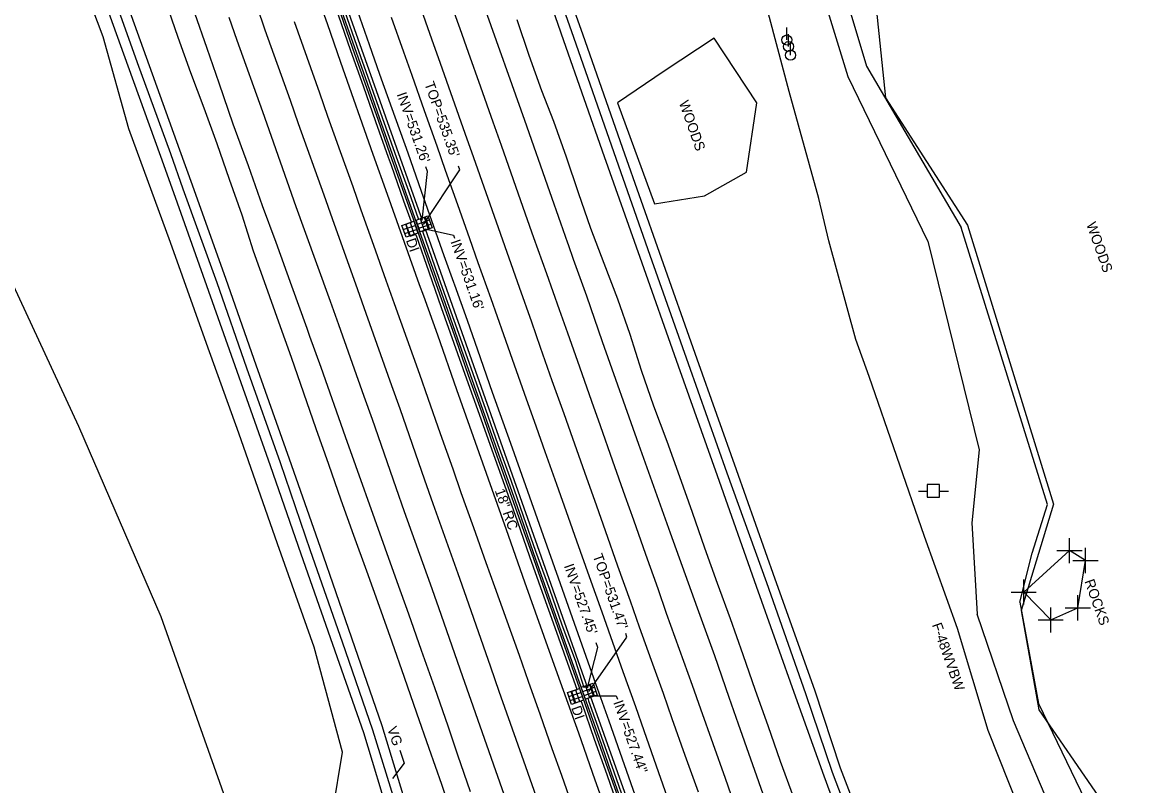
# Model space of a CAD drawing. Extents: x 2004847 to 2009016, y 1134161 to 1140101.
# Drawn here: x 2006650.7 to 2007096, y 1134403 to 1134706.5 of the extents above; entities that cross this region are included whole.
import ezdxf

# ---------------------------------------------------------------- set-up
doc = ezdxf.new("R2010")
doc.units = 0
for name, color, linetype in [('RD_EX_Conc', 7, 'Continuous'), ('RD_EX_DR_Inlet', 7, 'Continuous'), ('RD_EX_DR_Inlet_txCode', 7, 'Continuous'), ('RD_EX_DR_Pipe', 7, 'Continuous'), ('RD_EX_DR_Pipe_txCode', 7, 'Continuous'), ('RD_EX_Driveway', 7, 'Continuous'), ('RD_EX_DV_Prop_txCode', 7, 'Continuous'), ('RD_EX_Fence_Other', 7, 'Continuous'), ('RD_EX_Misc', 7, 'Continuous'), ('RD_EX_Pavement_Markings', 7, 'Continuous'), ('RD_EX_Road', 7, 'Continuous'), ('RD_EX_UT', 7, 'Continuous'), ('RD_EX_VEG', 7, 'Continuous'), ('RD_Sketch3', 7, 'Continuous')]:
    doc.layers.add(name, color=color, linetype=linetype)

msp = doc.modelspace()

# ---------------------------------------------------------------- linework, layer by layer
at = {"layer": 'RD_EX_Conc'}
for points in [[(2007008.76, 1134333.65), (2006993.63, 1134363.82), (2006975.89, 1134409.97), (2006965.78, 1134441.02), (2006950.02, 1134485.15), (2006934.64, 1134528.55), (2006918.96, 1134572.55), (2006904.01, 1134614.93), (2006889.45, 1134656.34), (2006873.52, 1134701.79), (2006859.53, 1134740.78), (2006845, 1134783.14), (2006828.98, 1134829.04), (2006813.77, 1134872.83), (2006798.81, 1134915.62), (2006782.15, 1134963.38), (2006767.46, 1135005.24), (2006753.34, 1135046.25), (2006752.31, 1135048.89), (2006751.51, 1135051.2), (2006736.87, 1135093.18), (2006721.7, 1135136.82), (2006709.9, 1135170.59)], [(2007001.61, 1134330.02), (2006986.35, 1134360.57), (2006969.5, 1134406.75), (2006958.22, 1134438.26), (2006942.49, 1134482.23), (2006927.03, 1134526.16), (2006911.49, 1134569.75), (2006896.31, 1134613.04), (2006882.16, 1134653.08), (2006865.99, 1134699.12), (2006852.4, 1134738.21), (2006837.28, 1134781.15), (2006821.3, 1134826.88), (2006806.03, 1134870.56), (2006791.16, 1134913.28), (2006774.61, 1134960.65), (2006760.24, 1135002.17), (2006744.89, 1135045.85), (2006729.14, 1135091.12), (2006713.78, 1135134.81), (2006702.17, 1135168.35)], [(2006812.01, 1134352.55), (2006804.85, 1134390.29), (2006793.78, 1134426.87), (2006781.64, 1134461.67), (2006769.18, 1134497.73), (2006756.9, 1134532.82), (2006743.7, 1134570.21), (2006731.7, 1134604.22), (2006718.31, 1134641.74), (2006713.33, 1134655.71), (2006700.01, 1134692.45), (2006688.72, 1134724.37), (2006675.5, 1134761.9)], [(2006804.07, 1134351.71), (2006797.18, 1134388.56), (2006786.48, 1134424.09), (2006774.14, 1134459.12), (2006761.55, 1134495.03), (2006749.36, 1134530.2), (2006736.12, 1134567.64), (2006724.06, 1134601.67), (2006710.86, 1134638.74), (2006705.69, 1134653.17), (2006692.76, 1134689), (2006681.14, 1134721.57), (2006668.03, 1134759.07)], [(2006777.01, 1134710.4), (2006782, 1134696.25), (2006787.02, 1134682.08), (2006792.02, 1134667.97), (2006796.98, 1134653.82), (2006802.35, 1134638.76), (2006808, 1134622.75), (2006813.01, 1134608.57), (2006818.04, 1134594.46), (2006822.99, 1134580.35), (2006827.98, 1134566.17), (2006833.03, 1134552.04), (2006838.05, 1134537.91), (2006843.04, 1134523.78), (2006848.09, 1134509.65), (2006853.08, 1134495.53), (2006858.41, 1134480.47), (2006863.41, 1134466.29), (2006868.44, 1134452.16), (2006874.13, 1134436.14), (2006879.1, 1134422.03), (2006884.12, 1134407.89), (2006889.12, 1134393.75)], [(2006777.73, 1134710.65), (2006782.72, 1134696.51), (2006787.75, 1134682.34), (2006792.72, 1134668.22), (2006797.72, 1134654.08), (2006803.07, 1134639.02), (2006808.72, 1134623), (2006813.75, 1134608.84), (2006818.74, 1134594.71), (2006823.73, 1134580.61), (2006828.73, 1134566.44), (2006833.75, 1134552.3), (2006838.79, 1134538.17), (2006843.78, 1134524.04), (2006848.8, 1134509.9), (2006853.79, 1134495.78), (2006859.1, 1134480.71), (2006864.14, 1134466.55), (2006869.15, 1134452.41), (2006874.85, 1134436.4), (2006879.82, 1134422.28), (2006884.82, 1134408.14), (2006889.83, 1134394)]]:
    msp.add_lwpolyline(points, dxfattribs=at)
at = {"layer": 'RD_EX_DR_Inlet'}
for p, q in [((2006807.76, 1134626.29), (2006812.49, 1134627.91)), ((2006808.81, 1134628.45), (2006810.44, 1134623.72)), ((2006810.42, 1134629), (2006812.04, 1134624.27)), ((2006802.15, 1134624.15), (2006806.88, 1134625.77)), ((2006802.7, 1134622.54), (2006807.43, 1134624.16)), ((2006803.21, 1134626.31), (2006804.83, 1134621.58)), ((2006804.81, 1134626.86), (2006806.44, 1134622.13)), ((2006808.31, 1134624.68), (2006813.04, 1134626.3)), ((2006869, 1134440.63), (2006870.62, 1134435.9)), ((2006870.61, 1134441.18), (2006872.23, 1134436.45)), ((2006873.46, 1134440.52), (2006878.19, 1134442.14)), ((2006874.02, 1134438.91), (2006878.75, 1134440.53)), ((2006874.52, 1134442.68), (2006876.14, 1134437.95)), ((2006876.13, 1134443.23), (2006877.75, 1134438.5)), ((2006867.94, 1134438.47), (2006872.67, 1134440.09)), ((2006868.5, 1134436.86), (2006873.22, 1134438.48))]:
    msp.add_line(p, q, dxfattribs=at)
for points in [[(2006803.22, 1134621.02), (2006801.6, 1134625.75), (2006806.33, 1134627.38), (2006807.95, 1134622.65)], [(2006808.83, 1134623.17), (2006807.21, 1134627.9), (2006811.94, 1134629.52), (2006813.56, 1134624.79)], [(2006869.01, 1134435.35), (2006867.39, 1134440.08), (2006872.12, 1134441.7), (2006873.74, 1134436.97)], [(2006874.54, 1134437.4), (2006872.91, 1134442.13), (2006877.64, 1134443.75), (2006879.26, 1134439.02)]]:
    msp.add_lwpolyline(points, close=True, dxfattribs=at)
at = {"layer": 'RD_EX_DR_Inlet_txCode'}
for points in [[(2006809.6, 1134627.85), (2006811.77, 1134647.25), (2006811.16, 1134648.99)], [(2006810.19, 1134626.14), (2006824.59, 1134647.89), (2006824.1, 1134649.29)], [(2006810.77, 1134624.41), (2006822.1, 1134621.88), (2006822.53, 1134620.66)], [(2006875.91, 1134440.4), (2006891.06, 1134462.06), (2006890.57, 1134463.46)], [(2006875.37, 1134441.93), (2006879.43, 1134457.98), (2006878.79, 1134459.78)], [(2006876.41, 1134438.8), (2006886.8, 1134438.69), (2006887.26, 1134437.4)]]:
    msp.add_lwpolyline(points, dxfattribs=at)
at = {"layer": 'RD_EX_DR_Pipe'}
for p, q in [((2006739.57, 1134825.25), (2006809.6, 1134627.85)), ((2006810.77, 1134624.41), (2006875.37, 1134441.93)), ((2006876.41, 1134438.8), (2006910.37, 1134343.42))]:
    msp.add_line(p, q, dxfattribs=at)
at = {"layer": 'RD_EX_Driveway'}
for points in [[(2007010.65, 1134619.47), (2006979.03, 1134684.79), (2006961.64, 1134741.36)], [(2006970.9, 1134740.44), (2006986.22, 1134689.04), (2007023.87, 1134624.93)], [(2007047.24, 1134476.04), (2007052.16, 1134495.5), (2007058.26, 1134514.81), (2007023.87, 1134624.93)], [(2007010.65, 1134619.47), (2007031.06, 1134536.55), (2007028.2, 1134507.51), (2007030.28, 1134471.18)], [(2007047.24, 1134476.04), (2007054.6, 1134435.72), (2007073.17, 1134397.21), (2007088.83, 1134358.42), (2007096.03, 1134334.59)], [(2007079.8, 1134330.74), (2007073.16, 1134353.09), (2007060.64, 1134391.35), (2007044.77, 1134428.83), (2007030.28, 1134471.18)]]:
    msp.add_lwpolyline(points, dxfattribs=at)
at = {"layer": 'RD_EX_DV_Prop_txCode'}
for p, q in [((2007066.97, 1134491.45), (2007066.97, 1134501.45)), ((2007061.97, 1134496.45), (2007071.97, 1134496.45)), ((2007073.32, 1134487.51), (2007073.32, 1134497.51)), ((2007068.32, 1134492.51), (2007078.32, 1134492.51)), ((2007048.78, 1134474.99), (2007048.78, 1134484.99)), ((2007043.78, 1134479.99), (2007053.78, 1134479.99)), ((2007070.27, 1134468.75), (2007070.27, 1134478.75)), ((2007059.5, 1134463.91), (2007059.5, 1134473.91)), ((2007065.27, 1134473.75), (2007075.27, 1134473.75)), ((2007054.5, 1134468.91), (2007064.5, 1134468.91))]:
    msp.add_line(p, q, dxfattribs=at)
at = {"layer": 'RD_EX_Fence_Other'}
for points in [[(2007063.77, 1134349.09), (2007051.32, 1134382.98), (2007034.66, 1134424.99), (2007022.46, 1134465.49), (2007009.27, 1134502.08), (2006987.27, 1134565.71), (2006982.09, 1134580.37), (2006971.28, 1134619.61), (2006967.26, 1134636.51), (2006955.53, 1134679.01), (2006933.1, 1134763.45), (2006921.61, 1134808.45), (2006913.35, 1134838.48), (2006889.85, 1134911.88), (2006879.83, 1134940.33), (2006864.22, 1134985.13), (2006847.99, 1135029.35), (2006842.47, 1135045.23)], [(2006781.02, 1134257.51), (2006758.13, 1134323.34), (2006734.53, 1134389.26), (2006705.85, 1134470.16), (2006673.2, 1134545.85), (2006633.71, 1134630.78), (2006600.8, 1134705.61), (2006545.88, 1134844.85), (2006510.38, 1134945.08)]]:
    msp.add_lwpolyline(points, dxfattribs=at)
at = {"layer": 'RD_EX_Misc'}
msp.add_lwpolyline([(2007059.5, 1134468.91), (2007070.27, 1134473.75), (2007073.32, 1134492.51), (2007066.97, 1134496.45), (2007048.78, 1134479.99)], close=True, dxfattribs=at)
at = {"layer": 'RD_EX_Pavement_Markings'}
for points in [[(2006761.15, 1134736.06), (2006771.82, 1134705.98), (2006777.23, 1134690.59), (2006790.01, 1134654.11), (2006795.73, 1134638.12), (2006808.48, 1134602.29), (2006810.13, 1134597.78), (2006815.7, 1134582.21), (2006823.33, 1134560.46), (2006837.37, 1134520.96), (2006843.05, 1134504.9), (2006850.38, 1134484.11), (2006854.57, 1134472.19), (2006861.41, 1134452.78), (2006871.77, 1134423.99), (2006878.28, 1134405.4), (2006883.4, 1134390.84), (2006889.14, 1134374.45), (2006894.32, 1134360.11), (2006902.43, 1134337.19), (2006906.68, 1134325.03), (2006910.08, 1134315.38), (2006961.34, 1134168.46)], [(2006819.59, 1134718.06), (2006824.56, 1134704.05), (2006827.89, 1134694.66), (2006832.78, 1134680.83), (2006837.67, 1134667), (2006840.98, 1134657.65), (2006845.81, 1134643.99), (2006850.64, 1134630.32), (2006853.95, 1134620.97), (2006859.01, 1134606.67), (2006864.07, 1134592.37), (2006867.35, 1134583.11), (2006872.13, 1134569.51), (2006876.91, 1134555.91), (2006880.37, 1134546.16), (2006885.29, 1134532.19), (2006890.21, 1134518.23), (2006893.61, 1134508.69), (2006898.44, 1134495.03), (2006903.27, 1134481.36), (2006906.7, 1134471.6), (2006911.84, 1134457.27), (2006916.98, 1134442.94), (2006920.27, 1134433.52), (2006925.17, 1134419.74), (2006930.07, 1134405.96), (2006933.59, 1134396.06)], [(2006971.5, 1134325.84), (2006967.94, 1134335.67), (2006965.04, 1134343.86), (2006960.52, 1134356.54), (2006952.36, 1134379.64), (2006946.03, 1134397.35), (2006935.38, 1134427.48), (2006931.68, 1134438.01), (2006925.92, 1134454.61), (2006919.03, 1134473.64), (2006908.39, 1134503.37), (2006895.77, 1134538.71), (2006881.3, 1134579.46), (2006875.08, 1134597.59), (2006869.84, 1134612.25), (2006867.8, 1134618.04), (2006867.58, 1134618.64), (2006864.8, 1134626.66), (2006860.44, 1134639.08), (2006850.41, 1134667.47), (2006845.37, 1134681.65), (2006839.16, 1134699.2), (2006832.85, 1134717.15)], [(2006743.96, 1134712.87), (2006747.16, 1134703.49), (2006757.16, 1134675.58), (2006760.38, 1134666.33), (2006770.51, 1134637.87), (2006773.91, 1134628.44), (2006783.92, 1134600.29), (2006787.22, 1134590.86), (2006797.43, 1134562.07), (2006800.7, 1134552.91), (2006810.57, 1134524.57), (2006813.83, 1134515.22), (2006823.78, 1134487.36), (2006827.07, 1134477.97), (2006836.8, 1134450.28), (2006840.09, 1134440.58), (2006849.89, 1134412.94), (2006853.18, 1134403.45), (2006863.05, 1134375.55), (2006866.41, 1134366.09), (2006876.69, 1134337.46), (2006880.32, 1134327.63), (2006936.22, 1134170.67)], [(2006782.95, 1134713.64), (2006788.58, 1134697.68), (2006792.73, 1134685.83), (2006797.61, 1134672.28), (2006803.91, 1134654.55), (2006809.27, 1134639.42), (2006818.26, 1134613.85), (2006822.06, 1134603.23), (2006822.47, 1134602.15), (2006827.48, 1134588.07), (2006831.6, 1134576.26), (2006837.53, 1134559.5), (2006844.76, 1134539.17), (2006850.71, 1134522.3), (2006856.93, 1134504.76), (2006864.46, 1134483.36), (2006868.41, 1134472.08), (2006878.54, 1134443.58), (2006883.84, 1134428.74), (2006897.79, 1134389.14)], [(2006808.44, 1134713.79), (2006813.32, 1134699.95), (2006816.76, 1134690.23), (2006821.69, 1134676.34), (2006826.62, 1134662.45), (2006830.07, 1134652.75), (2006834.99, 1134638.85), (2006839.91, 1134624.94), (2006843.32, 1134615.16), (2006848.21, 1134601.26), (2006853.1, 1134587.36), (2006856.59, 1134577.33), (2006861.25, 1134564.16), (2006865.91, 1134551), (2006869.39, 1134541.14), (2006874.14, 1134527.7), (2006878.89, 1134514.26), (2006882.34, 1134504.42), (2006887.31, 1134490.48), (2006892.28, 1134476.53), (2006895.96, 1134466.16), (2006900.67, 1134452.94), (2006905.38, 1134439.73), (2006908.93, 1134429.76), (2006914.12, 1134415.17), (2006919.32, 1134400.58)], [(2006719.13, 1134710.22), (2006724, 1134696.26), (2006728.85, 1134682.46), (2006734.43, 1134666.2), (2006740.42, 1134649.61), (2006746.1, 1134633.69), (2006751.45, 1134619.12), (2006757.71, 1134601.68), (2006763.8, 1134584.91), (2006764.91, 1134581.77), (2006769.32, 1134569.35), (2006779.05, 1134541.77), (2006794.8, 1134497.51), (2006799.62, 1134484.15), (2006804.16, 1134471.29), (2006809.29, 1134456.85), (2006814.52, 1134442.04), (2006819.82, 1134426.82), (2006823.72, 1134415.28), (2006828.76, 1134400.65)], [(2006732.74, 1134708.5), (2006736.01, 1134699.34), (2006746.11, 1134671.03), (2006749.58, 1134661.19), (2006759.46, 1134633.21), (2006762.72, 1134624.11), (2006773.08, 1134595.66), (2006776.33, 1134586.35), (2006786.48, 1134557.89), (2006789.7, 1134548.67), (2006799.21, 1134521.6), (2006802.52, 1134512.03), (2006812.88, 1134483.28), (2006816.15, 1134473.85), (2006825.71, 1134446.36), (2006828.93, 1134437.07), (2006838.79, 1134409.05), (2006842.06, 1134399.64), (2006851.92, 1134371.56), (2006855.13, 1134362.22), (2006865.49, 1134333.56), (2006868.8, 1134324.26), (2006923.13, 1134171.83)], [(2006797.26, 1134708.59), (2006802.21, 1134694.72), (2006805.49, 1134685.43), (2006810.47, 1134671.41), (2006815.46, 1134657.39), (2006818.81, 1134647.72), (2006823.62, 1134634.11), (2006828.43, 1134620.5), (2006831.83, 1134610.97), (2006836.9, 1134596.66), (2006841.97, 1134582.35), (2006845.41, 1134572.56), (2006850.18, 1134559.11), (2006854.95, 1134545.66), (2006858.4, 1134535.91), (2006863.01, 1134522.87), (2006867.63, 1134509.83), (2006870.95, 1134500.42), (2006876.01, 1134486.24), (2006881.06, 1134472.07), (2006884.49, 1134462.34), (2006889.44, 1134448.39), (2006894.38, 1134434.44), (2006897.71, 1134424.97), (2006903.58, 1134408.31), (2006909.45, 1134391.65)], [(2006758.78, 1134706.76), (2006763.78, 1134692.6), (2006768.78, 1134678.43), (2006772.07, 1134669.14), (2006777.05, 1134655.17), (2006782.04, 1134641.2), (2006785.32, 1134631.95), (2006790.28, 1134617.96), (2006795.24, 1134603.97), (2006798.51, 1134594.7), (2006803.52, 1134580.65), (2006808.52, 1134566.6), (2006811.9, 1134557.06), (2006816.86, 1134543.01), (2006821.82, 1134528.96), (2006825.06, 1134519.61), (2006830.01, 1134505.68), (2006834.96, 1134491.75), (2006838.38, 1134482.19), (2006843.28, 1134468.53), (2006848.18, 1134454.87), (2006851.78, 1134444.63), (2006856.52, 1134431.24), (2006861.25, 1134417.84), (2006865.02, 1134407.18), (2006869.79, 1134393.58)]]:
    msp.add_lwpolyline(points, dxfattribs=at)
at = {"layer": 'RD_EX_Road'}
msp.add_line((2006809.72, 1134623.45), (2006812.6, 1134624.42), dxfattribs=at)
for points in [[(2006706.11, 1135169.52), (2006717.88, 1135136.12), (2006733.28, 1135092.09), (2006748.47, 1135047.58), (2006763.79, 1135003.81), (2006778.27, 1134961.83), (2006795.07, 1134914.22), (2006809.69, 1134871.89), (2006820.71, 1134840.68), (2006828.76, 1134817.54), (2006841.37, 1134782.12), (2006855.99, 1134739.87), (2006869.8, 1134700.59), (2006885.78, 1134654.79), (2006900.16, 1134613.89), (2006915.32, 1134570.8), (2006930.8, 1134527.38), (2006946.57, 1134483.83), (2006961.99, 1134439.72), (2006972.66, 1134408.4), (2006989.95, 1134362.61), (2007005.15, 1134331.63)], [(2006738.68, 1134824.19), (2006743.68, 1134810.08), (2006748.69, 1134795.91), (2006753.69, 1134781.82), (2006758.72, 1134767.66), (2006763.7, 1134753.52), (2006768.72, 1134739.36), (2006773.7, 1134725.23), (2006778.72, 1134711.1), (2006783.71, 1134696.96), (2006788.76, 1134682.81), (2006793.68, 1134668.67), (2006798.72, 1134654.54), (2006804.15, 1134639.5), (2006808.12, 1134628.08)], [(2006805.41, 1134627.07), (2006802.4, 1134635.38), (2006797.44, 1134649.54), (2006796.3, 1134652.82), (2006791.21, 1134666.89), (2006786.29, 1134681.06), (2006781.31, 1134695.21), (2006776.32, 1134709.37), (2006771.34, 1134723.51), (2006766.31, 1134737.64), (2006761.28, 1134751.77), (2006756.29, 1134765.92), (2006751.32, 1134780.04), (2006746.33, 1134794.18), (2006741.34, 1134808.35), (2006736.33, 1134822.48), (2006736.07, 1134823.23)], [(2006684.95, 1134722.62), (2006696.29, 1134690.56), (2006709.59, 1134654.29), (2006714.5, 1134640.35), (2006728.04, 1134603.03), (2006739.84, 1134569.14), (2006753.16, 1134531.45), (2006765.07, 1134496.51), (2006777.8, 1134460.22), (2006789.93, 1134425.26), (2006801, 1134389.3), (2006808.01, 1134352.31), (2006812.76, 1134314.88), (2006816.12, 1134274.41), (2006818.9, 1134250.57)], [(2006707.58, 1134714.75), (2006712.54, 1134700.63), (2006717.61, 1134686.5), (2006722.85, 1134672.51), (2006727.97, 1134658.27), (2006732.92, 1134644.14), (2006737.93, 1134629.92), (2006742.52, 1134615.71), (2006747.43, 1134601.54), (2006752.52, 1134587.39), (2006757.5, 1134573.32), (2006762.44, 1134559.18), (2006767.43, 1134545.04), (2006772.34, 1134530.84), (2006777.28, 1134516.68), (2006782.37, 1134502.57), (2006787.45, 1134488.41), (2006792.5, 1134474.37), (2006797.61, 1134460.24), (2006802.54, 1134446.1), (2006807.44, 1134431.98), (2006812.34, 1134417.89), (2006817.28, 1134403.67), (2006822.12, 1134389.44)], [(2006847.24, 1134707.62), (2006852.07, 1134693.46), (2006857.08, 1134679.34), (2006861.88, 1134667.22), (2006866.87, 1134653.08), (2006871.63, 1134638.84), (2006876.57, 1134624.63), (2006881.89, 1134610.72), (2006887.23, 1134596.55), (2006892.14, 1134582.5), (2006896.73, 1134568.22), (2006901.64, 1134554.05), (2006906.84, 1134540), (2006911.91, 1134525.89), (2006916.92, 1134511.75), (2006921.86, 1134497.6), (2006926.95, 1134483.49), (2006932.02, 1134469.42), (2006937.14, 1134455.16), (2006942.07, 1134441.05), (2006947.05, 1134426.92), (2006951.94, 1134412.74), (2006957.06, 1134398.69)], [(2006812.6, 1134624.42), (2006810.93, 1134629), (2006808.12, 1134628.08)], [(2006807.16, 1134622.18), (2006804.76, 1134621.35), (2006803.17, 1134626.25), (2006805.41, 1134627.07)], [(2006809.72, 1134623.45), (2006814.74, 1134609.29), (2006819.76, 1134595.17), (2006824.74, 1134581.06), (2006829.73, 1134566.89), (2006834.76, 1134552.75), (2006839.77, 1134538.62), (2006844.84, 1134524.51), (2006849.74, 1134510.33), (2006854.73, 1134496.2), (2006860.22, 1134481.19), (2006865.22, 1134467.02), (2006870.47, 1134452.97), (2006873.94, 1134442.07)], [(2006871.21, 1134441.26), (2006867.52, 1134451.64), (2006862.54, 1134465.74), (2006857.47, 1134479.86), (2006852.48, 1134494.01), (2006847.51, 1134508.16), (2006842.52, 1134522.3), (2006837.5, 1134536.44), (2006832.44, 1134550.56), (2006827.46, 1134564.68), (2006822.4, 1134578.8), (2006817.39, 1134592.97), (2006812.47, 1134607.13), (2006807.48, 1134621.27), (2006807.16, 1134622.18)], [(2006872.87, 1134436.63), (2006870.36, 1134435.79), (2006868.87, 1134440.42), (2006871.21, 1134441.26)], [(2006875.43, 1134437.82), (2006878.11, 1134438.78), (2006876.59, 1134442.92), (2006873.94, 1134442.07)], [(2006906.36, 1134341.89), (2006903.22, 1134350.76), (2006898.21, 1134364.93), (2006893.17, 1134379), (2006888.11, 1134393.13), (2006883.19, 1134407.29), (2006878.2, 1134421.43), (2006873.22, 1134435.63), (2006872.87, 1134436.63)], [(2006875.43, 1134437.82), (2006875.77, 1134436.81), (2006880.79, 1134422.7), (2006885.79, 1134408.56), (2006890.8, 1134394.42), (2006895.8, 1134380.27), (2006900.83, 1134366.13), (2006905.79, 1134351.99), (2006908.81, 1134343.37)]]:
    msp.add_lwpolyline(points, dxfattribs=at)
at = {"layer": 'RD_EX_UT'}
for p, q in [((2006954.58, 1134699.47), (2006954.58, 1134704.47)), ((2006955.3, 1134696.85), (2006955.3, 1134701.85)), ((2006956.1, 1134693.43), (2006956.1, 1134698.43)), ((2007015.33, 1134522.72), (2007010.33, 1134522.72)), ((2007010.33, 1134522.72), (2007010.33, 1134517.72)), ((2007015.33, 1134517.72), (2007015.33, 1134522.72)), ((2007006.9, 1134520.16), (2007010.37, 1134520.16)), ((2007010.33, 1134517.72), (2007015.33, 1134517.72)), ((2007015.26, 1134520.16), (2007018.9, 1134520.16))]:
    msp.add_line(p, q, dxfattribs=at)
for centre in [(2006954.58, 1134699.47), (2006955.3, 1134696.85), (2006956.1, 1134693.43)]:
    msp.add_circle(centre, 2, dxfattribs=at)
at = {"layer": 'RD_EX_VEG'}
for points in [[(2006945.5, 1134928.28), (2006935.9, 1134899.95), (2006940.34, 1134863.91), (2006963.95, 1134836.23), (2006984.21, 1134807.76), (2006970.59, 1134790.59), (2006973.32, 1134745.76), (2006990.14, 1134712.21), (2006993.77, 1134676.44), (2007026.48, 1134625.81), (2007060.61, 1134514.95)], [(2006784.26, 1134257.11), (2006772.96, 1134295.43), (2006756.99, 1134333.38), (2006766.92, 1134353.24), (2006774.06, 1134393.08), (2006777.93, 1134416.4), (2006766.71, 1134458.14), (2006752.13, 1134499.13), (2006736.73, 1134543.18), (2006723.95, 1134578.76), (2006709.63, 1134619.01), (2006693, 1134664.21), (2006682.82, 1134700.75), (2006669.68, 1134735.59)], [(2006902.05, 1134634.37), (2006921.91, 1134637.49), (2006938.58, 1134646.98), (2006942.74, 1134674.53), (2006925.71, 1134700.18), (2006905.89, 1134687.02), (2006887.24, 1134674.51), (2006902.05, 1134634.37)], [(2007060.61, 1134514.95), (2007047.76, 1134472.69), (2007054.79, 1134433.13), (2007078.46, 1134398.75), (2007095.56, 1134360.4)]]:
    msp.add_lwpolyline(points, dxfattribs=at)
at = {"layer": 'RD_Sketch3'}
msp.add_lwpolyline([(2006800.71, 1134417.18), (2006802.53, 1134412.01), (2006797.88, 1134405.81)], dxfattribs=at)

# ---------------------------------------------------------------- texts
at = {"layer": 'RD_EX_DR_Inlet_txCode'}
for s, p in [("TOP=535.35'", (2006810.46, 1134682.11)), ("INV=531.26'", (2006799.46, 1134677.9)), ('DI', (2006803.13, 1134619.84)), ("INV=531.16'", (2006820.85, 1134619.33)), ("TOP=531.47'", (2006877.38, 1134494.42)), ("INV=527.45'", (2006865.94, 1134490.41)), ("INV=527.44''", (2006885.56, 1134436.15)), ('DI', (2006868.86, 1134433.94))]:
    msp.add_text(s, height=4, rotation=289.4494, dxfattribs=at).set_placement(p)
at = {"layer": 'RD_EX_DR_Pipe_txCode'}
msp.add_text('18" RC', height=4, rotation=289.4494, dxfattribs=at).set_placement((2006838.45, 1134520.33))
at = {"layer": 'RD_Sketch3'}
for s, p in [('WOODS', (2006911.66, 1134674.58)), ('WOODS', (2007073.58, 1134626.25)), ('ROCKS', (2007072.87, 1134484.3)), ('F-48WVBW', (2007012.24, 1134466.97)), ('VG', (2006795.63, 1134425.7))]:
    msp.add_text(s, height=4, rotation=289.4494, dxfattribs=at).set_placement(p)

doc.saveas('drawing.dxf')
